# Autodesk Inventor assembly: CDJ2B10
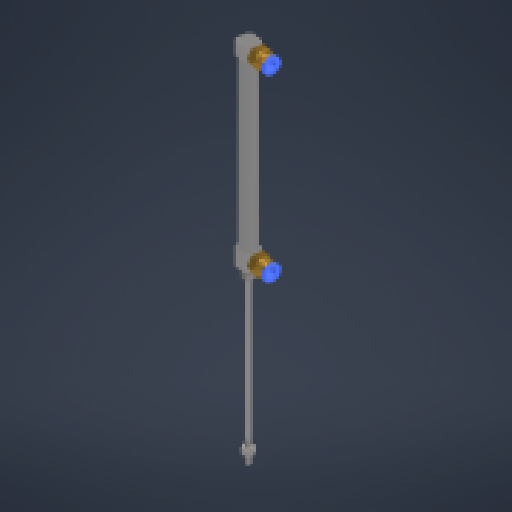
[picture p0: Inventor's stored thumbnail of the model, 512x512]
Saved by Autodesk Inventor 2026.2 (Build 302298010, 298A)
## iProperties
Created: 2026-05
Part Number: CDJ2B10
Document SubType Name: Assembly
Designer: work
Author: work
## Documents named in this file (3)
- C:\Users\work\Desktop\ARD_v1\ARD_hardware\PneumaticGripper_v1\Pneumatic fitting\CDJ2B10_100\CDJ2B10.iam
- C:\Users\work\Desktop\ARD_v1\ARD_hardware\PneumaticGripper_v1\Pneumatic fitting\CDJ2B10_100\CDJ2B10_Body.ipt
- C:\Users\work\Desktop\ARD_v1\ARD_hardware\PneumaticGripper_v1\Pneumatic fitting\PC6-M5.ipt
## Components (3 placed, 2 different names)
1. CDJ2B10_Body:1
2. PC6-M5:1
3. PC6-M5:2
